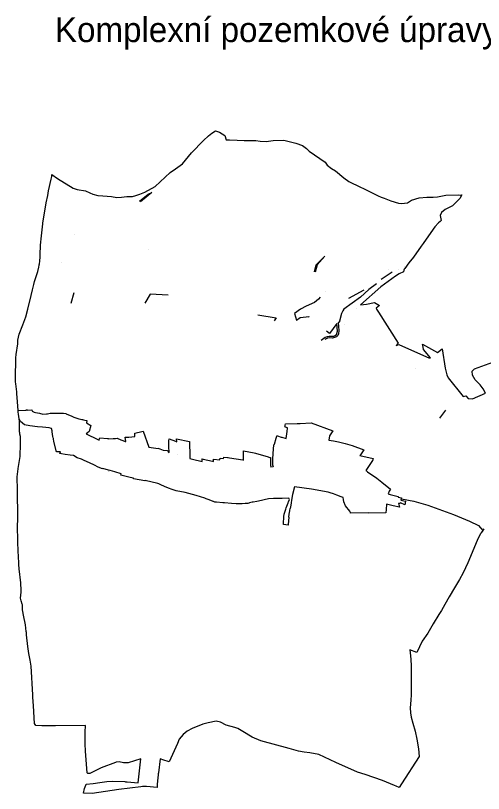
# Model space of a CAD drawing. Extents: x -598799 to -595054, y -1105067 to -1101467.
# Drawn here: x -598799 to -596632, y -1105067 to -1101467 of the extents above; entities that cross this region are included whole.
import ezdxf

# ---------------------------------------------------------------- set-up
doc = ezdxf.new("R2010")
doc.units = 0
for name, color, linetype in [('CESTY', 7, 'Continuous'), ('LES_ZV', 7, 'Continuous'), ('Level 255', 7, 'Continuous'), ('OVNE_PRE', 7, 'Continuous'), ('OVNE_SET', 7, 'Continuous'), ('OVNI_PRE', 7, 'Continuous'), ('OVNI_SET', 7, 'Continuous')]:
    doc.layers.add(name, color=color, linetype=linetype)

msp = doc.modelspace()

# ---------------------------------------------------------------- linework, layer by layer
at = {"layer": 'CESTY'}
msp.add_lwpolyline([(-597012.4, -1103704), (-596954.5, -1103714.7), (-596889.9, -1103733), (-596771.3, -1103775.4), (-596697.2, -1103807), (-596654.8, -1103827.5), (-596634.7, -1103849.3)], dxfattribs=at)
at = {"layer": 'LES_ZV'}
for p, q in [((-598529.5, -1102749.5), (-598542.9, -1102798.7)), ((-597186.3, -1102737.9), (-597257.2, -1102776.5)), ((-597677, -1102852.1), (-597592.2, -1102865.4)), ((-597592.2, -1102865.4), (-597601.3, -1102880.2)), ((-597345.5, -1102937.5), (-597358.4, -1102927.2)), ((-596807.4, -1103293.5), (-596835.8, -1103330.1))]:
    msp.add_line(p, q, dxfattribs=at)
for points in [[(-598225.5, -1102326.3), (-598185.7, -1102294.1), (-598167.7, -1102285.4), (-598220.4, -1102328.6)], [(-597415, -1102652.4), (-597406.7, -1102620.3), (-597367.2, -1102580.1), (-597402.4, -1102620.7), (-597411.3, -1102655.1)], [(-597054.7, -1102654.7), (-597078.6, -1102669.1), (-597105.3, -1102688.8)], [(-597128.3, -1102708.9), (-597162.5, -1102734.2), (-597201.2, -1102769.4), (-597278.6, -1102825.5), (-597283.1, -1102833.7), (-597289.6, -1102846.4), (-597300.9, -1102887.5), (-597305.6, -1102887.7), (-597302.5, -1102924.4)], [(-598092, -1102760.7), (-598175.9, -1102755.8), (-598199.8, -1102798.4)], [(-597387.8, -1102770.8), (-597396.2, -1102779.4), (-597414.6, -1102794.2), (-597453.4, -1102811), (-597479.2, -1102825.4), (-597507.2, -1102845.6), (-597498.6, -1102876.1), (-597481, -1102863.7)], [(-597481, -1102863.7), (-597439.9, -1102859), (-597441.8, -1102862)], [(-597308.9, -1102927.5), (-597311.3, -1102891.3), (-597345.5, -1102937.5)], [(-597384.3, -1102968.8), (-597371.5, -1102959.6), (-597364.9, -1102955), (-597355.1, -1102951.8), (-597347.4, -1102951), (-597332.8, -1102950.8), (-597325, -1102950), (-597319.5, -1102947.8), (-597313.5, -1102943), (-597310.5, -1102937.5), (-597308.9, -1102927.5)], [(-597302.5, -1102924.4), (-597304.3, -1102940.1), (-597307, -1102947.1), (-597312.1, -1102954), (-597330.8, -1102959.5), (-597345.8, -1102958.4), (-597354, -1102959.9), (-597360.7, -1102962.4), (-597366.5, -1102965.4)]]:
    msp.add_lwpolyline(points, dxfattribs=at)
at = {"layer": 'Level 255'}
for p, q in [((-598184.5, -1102548.9), (-598184.5, -1102548.9)), ((-598655.5, -1103310.2), (-598655.5, -1103310.2)), ((-598564.1, -1103309.6), (-598564.1, -1103309.6)), ((-598538.8, -1103321.3), (-598538.8, -1103321.3)), ((-598412.3, -1103431.9), (-598412.3, -1103431.9)), ((-597546.5, -1103424.8), (-597546.5, -1103424.8)), ((-597311.1, -1103438.4), (-597311.1, -1103438.4)), ((-598530.5, -1103503.4), (-598530.5, -1103503.4)), ((-597935, -1103531.2), (-597935, -1103531.2)), ((-597742.8, -1103524.4), (-597742.8, -1103524.4)), ((-597608, -1103526.3), (-597608, -1103526.3)), ((-597608, -1103526.3), (-597608, -1103526.3)), ((-597545.7, -1103745.5), (-597545.7, -1103745.5))]:
    msp.add_line(p, q, dxfattribs=at)
at = {"layer": 'OVNE_PRE'}
for p, q in [((-596747.9, -1102297.1), (-596737.9, -1102297.3)), ((-598525.3, -1102480.3), (-598525.3, -1102480.3)), ((-598184.5, -1102548.9), (-598184.5, -1102548.9)), ((-598584.3, -1102610.6), (-598584.3, -1102610.6)), ((-597027.4, -1102643.9), (-597027.4, -1102643.9)), ((-596998.7, -1102626.4), (-596998.7, -1102626.4)), ((-597363.3, -1102745.5), (-597363.3, -1102745.5)), ((-597202.4, -1102804.9), (-597202.4, -1102804.9)), ((-597276.6, -1102895.5), (-597276.6, -1102895.5)), ((-597007.7, -1102996.6), (-596884.6, -1103051.3)), ((-596945.3, -1103100), (-596945.3, -1103100)), ((-596796, -1103143.9), (-596725.5, -1103230.3)), ((-598368, -1103425), (-598368, -1103425)), ((-598336.9, -1103423.4), (-598336.9, -1103423.4)), ((-598328.9, -1103423), (-598328.9, -1103423)), ((-597992, -1103516.2), (-597992, -1103516.2))]:
    msp.add_line(p, q, dxfattribs=at)
for points in [[(-598673, -1102430.8), (-598672.8, -1102427.8), (-598657.9, -1102333.7), (-598650.3, -1102299.5), (-598646.6, -1102277.3), (-598634, -1102223.4), (-598631.6, -1102212.3), (-598631.2, -1102203.2), (-598605.5, -1102220.4), (-598532.4, -1102265.7), (-598513.8, -1102271.9), (-598474.8, -1102278.1), (-598455.4, -1102287.4), (-598440.6, -1102293.3), (-598417.9, -1102299.4), (-598394.7, -1102301.3), (-598354.3, -1102304.4), (-598330.4, -1102308.4), (-598308.6, -1102307.5), (-598283.3, -1102304.6), (-598257.4, -1102303.9), (-598242.1, -1102299.6), (-598223, -1102293.9), (-598200.3, -1102284.1), (-598153.3, -1102257.4), (-598105.8, -1102214.5), (-598083.2, -1102193.6), (-598059.2, -1102176.2), (-598026.3, -1102153.8), (-597998, -1102118.5), (-597985, -1102102.2), (-597928.8, -1102045.6), (-597905.9, -1102023.6), (-597890.8, -1102010.8), (-597873.2, -1101999.7), (-597854.5, -1102006.4), (-597829.7, -1102021.8), (-597823.8, -1102041.5), (-597808.8, -1102041.3), (-597772.1, -1102043.3), (-597741.1, -1102044.8), (-597718.6, -1102045.3), (-597686.7, -1102045.6), (-597666.1, -1102048.5), (-597639.1, -1102050.1), (-597606.1, -1102045.7), (-597556.4, -1102044.3), (-597500.7, -1102057.7), (-597470.7, -1102068.3), (-597452, -1102081.7), (-597439.5, -1102094.8), (-597365.8, -1102145.8), (-597356.7, -1102158.7), (-597335.8, -1102174.4), (-597317.3, -1102185.5), (-597279.6, -1102217.4), (-597255.5, -1102234.1), (-597201.1, -1102260.6), (-597188.2, -1102266.5), (-597169.4, -1102276.9), (-597134.9, -1102293.7), (-597120.1, -1102300.7), (-597106.2, -1102307.1), (-597092.2, -1102311.9), (-597061, -1102324.5), (-597025.4, -1102334.6), (-597012, -1102336.4), (-596983.8, -1102334), (-596964.7, -1102321.1), (-596930.5, -1102310.1), (-596895, -1102307.6), (-596864.8, -1102307.2), (-596845.6, -1102306.2), (-596807, -1102298.2), (-596747.9, -1102297.1)], [(-598696.8, -1102650.7), (-598691.9, -1102630.5), (-598690.1, -1102622.7), (-598689.3, -1102619.5), (-598689, -1102618.2), (-598686.7, -1102600.1), (-598685.7, -1102586.2), (-598684.9, -1102573.8), (-598683.9, -1102529.1), (-598678.8, -1102486.8), (-598673, -1102430.8)], [(-598772.6, -1104133.3), (-598773.1, -1104124.2), (-598774.6, -1104095.6), (-598775, -1104091.5), (-598782.4, -1104026.6), (-598784.6, -1104007.1), (-598786.3, -1103963.9), (-598786.9, -1103951), (-598787.9, -1103896.2), (-598790, -1103831.6), (-598789.4, -1103796.3), (-598789.3, -1103791.6), (-598790.8, -1103663.4), (-598791, -1103601.5), (-598787.3, -1103564.4), (-598787.2, -1103562.4), (-598778.6, -1103508.1), (-598777.6, -1103487.3), (-598776.5, -1103468.1), (-598776.5, -1103458.9), (-598776.6, -1103446.6), (-598776.6, -1103442.7), (-598776.6, -1103442.3), (-598776.7, -1103421), (-598776.7, -1103414.7), (-598778.7, -1103403.6), (-598779.2, -1103400.9), (-598779.7, -1103398.1), (-598780.6, -1103393), (-598781, -1103391), (-598780.7, -1103365.3), (-598780.5, -1103350.6), (-598780.5, -1103345.6), (-598782.6, -1103332.4), (-598785.9, -1103311.1), (-598787.1, -1103301.7), (-598787.4, -1103299.2), (-598787.7, -1103295.1), (-598790.1, -1103254.7), (-598793.3, -1103216.5), (-598793.8, -1103209.5), (-598794, -1103208.1), (-598798.1, -1103171.4), (-598799.2, -1103161.8), (-598799.2, -1103153.4), (-598799.2, -1103136.3), (-598799.2, -1103132.9), (-598798.1, -1103066.4), (-598797.4, -1103050.3), (-598795.8, -1103036), (-598789, -1102986.1), (-598788.9, -1102968.5), (-598782.8, -1102941.9), (-598765.3, -1102897.4), (-598751.7, -1102860.9), (-598742.5, -1102825.1), (-598726.6, -1102763.1), (-598720.2, -1102735.8), (-598714.5, -1102710.9), (-598711.2, -1102697), (-598699.8, -1102660.2), (-598696.8, -1102650.7)], [(-597202.4, -1102804.9), (-597174.6, -1102802.1), (-597137.5, -1102795.5), (-597113.2, -1102807.9), (-597129.2, -1102821.6), (-597126.9, -1102825.6), (-597118.8, -1102839.5), (-597027.8, -1102982.6), (-597035.8, -1102993.1), (-597023.7, -1102988.4), (-597007.7, -1102996.6)], [(-596884.6, -1103051.3), (-596876.7, -1103050.5), (-596909.5, -1103012.1), (-596913.5, -1102992.2), (-596914.4, -1102987.9)], [(-596914.4, -1102987.9), (-596845.8, -1103026.5), (-596824.1, -1103009.7)], [(-596824.1, -1103009.7), (-596809.4, -1103098.9), (-596802.3, -1103129.4), (-596796, -1103143.9)], [(-596630.9, -1103842.5), (-596633.6, -1103846.6), (-596638.4, -1103853.9), (-596639.7, -1103855.7), (-596642.5, -1103860), (-596643.7, -1103861.8), (-596644.4, -1103862.9), (-596645.8, -1103865.1), (-596658.9, -1103889.1), (-596684.8, -1103951.4), (-596705.1, -1103999.9), (-596725.9, -1104046.1), (-596742.8, -1104077.3), (-596765.7, -1104114.8), (-596790.8, -1104157.4), (-596811.2, -1104192), (-596826.8, -1104219.5), (-596839.4, -1104238.1), (-596865.6, -1104281.1), (-596890.2, -1104325.5), (-596915.4, -1104362.7), (-596941.2, -1104414.1), (-596972.6, -1104402.5), (-596969.6, -1104430.2), (-596968, -1104446.1), (-596967.3, -1104476.7), (-596967.7, -1104528.2), (-596967.7, -1104577.9), (-596967.7, -1104609.8), (-596969.3, -1104635.6), (-596971.4, -1104671.2), (-596970.3, -1104694.2)], [(-598767.8, -1104193.9), (-598768.6, -1104190.8), (-598773.1, -1104174.8), (-598776.5, -1104162.6), (-598772.9, -1104135.5), (-598772.6, -1104133.3)], [(-598767.1, -1104216.9), (-598767.2, -1104213.4), (-598767.7, -1104196.1), (-598767.8, -1104193.9)], [(-598748.1, -1104332.2), (-598749.2, -1104321.3), (-598749.8, -1104316.7), (-598753.2, -1104285.9), (-598762.1, -1104241.8), (-598765.5, -1104224.6), (-598767.1, -1104216.9)], [(-598476.6, -1104783), (-598475.8, -1104753), (-598614, -1104753.8), (-598665.8, -1104754.1), (-598677.9, -1104753.4), (-598705.8, -1104751.9), (-598711.2, -1104743.2), (-598716.2, -1104660.6), (-598718.6, -1104621.6), (-598719.3, -1104609.8), (-598727.2, -1104477), (-598732.1, -1104449.2), (-598737.6, -1104418.4), (-598743, -1104387.3), (-598748.1, -1104332.2)], [(-596970.3, -1104694.2), (-596966.4, -1104713.6), (-596959.8, -1104740.9)], [(-596930.7, -1104896.4), (-597012.1, -1105022.2), (-597023.3, -1105039.1), (-597035.8, -1105033), (-597043.7, -1105029.7), (-597100.4, -1105007.3), (-597180.1, -1104978.9), (-597215.8, -1104967.7), (-597315.6, -1104923.9), (-597395.4, -1104887.1), (-597436.6, -1104878.1), (-597437, -1104879.4), (-597462.4, -1104876.2), (-597489.4, -1104870.4), (-597532.7, -1104859.1), (-597663.9, -1104823.1), (-597703, -1104806.2), (-597746, -1104779.5), (-597769, -1104766.8), (-597784.2, -1104761.6), (-597824.5, -1104751.1), (-597850.6, -1104737.6), (-597870.5, -1104732.1), (-597907.7, -1104739.3), (-597931.1, -1104746.3), (-597980.5, -1104765.4), (-598004.3, -1104778), (-598022.2, -1104793.8), (-598041, -1104815.2), (-598049.8, -1104835.6), (-598087.1, -1104921), (-598091.8, -1104919.5), (-598112, -1104913), (-598129.7, -1104907.3), (-598137.5, -1104971.2), (-598138.1, -1104976.1), (-598139.3, -1104986), (-598139.7, -1104989.6), (-598140.2, -1104993.8), (-598143.7, -1105024.5), (-598143.3, -1105033.1), (-598143.1, -1105039.2), (-598192.1, -1105034.7), (-598210.8, -1105035.3), (-598219.1, -1105035.5), (-598320.5, -1105048.9), (-598443.7, -1105066.7), (-598484, -1105065.9), (-598480.5, -1105044), (-598473, -1105027.8)], [(-596959.8, -1104740.9), (-596948.8, -1104779.1), (-596940.6, -1104815.5), (-596933.4, -1104860.2), (-596930.7, -1104896.4)], [(-598475.5, -1104871.2), (-598476.1, -1104837.6), (-598476.2, -1104827.6), (-598476.6, -1104783)], [(-598408.3, -1105015.9), (-598376.8, -1105011), (-598351.9, -1105009.4), (-598293.4, -1105012.1), (-598290.6, -1105012.3), (-598281.9, -1105012.9), (-598231.8, -1105017.5), (-598218.3, -1104906.7), (-598277.5, -1104925.5), (-598298.9, -1104925.5), (-598318.8, -1104920.9), (-598333, -1104921.8), (-598336.2, -1104923), (-598402.3, -1104948.9), (-598455.3, -1104974.9), (-598463.7, -1104974.9), (-598468, -1104971.1), (-598475.5, -1104871.2)], [(-598473, -1105027.8), (-598471.5, -1105024.4), (-598439.8, -1105021.1), (-598408.3, -1105015.9)]]:
    msp.add_lwpolyline(points, dxfattribs=at)
at = {"layer": 'OVNE_SET'}
for p, q in [((-598673, -1102430.8), (-598673, -1102430.8)), ((-597070.1, -1102641.2), (-597070.1, -1102641.2)), ((-597221.8, -1102820.5), (-597221.8, -1102820.5)), ((-598655.7, -1103310.2), (-598655.7, -1103310.2))]:
    msp.add_line(p, q, dxfattribs=at)
for points in [[(-596737.9, -1102297.3), (-596731.6, -1102297.2), (-596742.2, -1102313), (-596775.4, -1102347.9), (-596810.2, -1102364.8), (-596826.1, -1102378.9), (-596832.9, -1102392.9), (-596829.6, -1102407.2), (-596827.8, -1102415.3), (-596832.8, -1102419.4), (-596840.5, -1102426.4), (-596858.1, -1102444.9), (-596886.4, -1102485.7), (-596911.3, -1102521.8), (-596920, -1102534.1), (-596955.9, -1102584.5), (-596977.4, -1102610.5), (-596996.2, -1102637.5), (-596998.9, -1102640.9), (-597001.4, -1102644.7), (-597002.1, -1102652.6), (-597021.9, -1102661.8)], [(-597021.9, -1102661.8), (-597039.2, -1102673.1), (-597106.8, -1102722.1), (-597202.4, -1102804.9)], [(-596725.5, -1103230.3), (-596713.2, -1103227.4), (-596703.2, -1103238.7), (-596683, -1103241.1), (-596622.8, -1103214.7), (-596632.8, -1103193.8), (-596648.2, -1103175.4), (-596670.2, -1103152.4), (-596682.9, -1103131.8), (-596684.4, -1103113), (-596673.2, -1103102.5), (-596623.5, -1103083.9), (-596589.3, -1103071.3), (-596560, -1103062.9), (-596527.1, -1103054.2), (-596488.9, -1103043.6)]]:
    msp.add_lwpolyline(points, dxfattribs=at)
at = {"layer": 'OVNI_PRE'}
for p, q in [((-598706.2, -1103304.2), (-598689, -1103307.4)), ((-598639.1, -1103307.3), (-598629.4, -1103307.3)), ((-598629.4, -1103307.3), (-598619.5, -1103307.4)), ((-598412.3, -1103431.9), (-598412.3, -1103431.9)), ((-598368, -1103425), (-598368, -1103425)), ((-598048.2, -1103499.6), (-598048.2, -1103499.6)), ((-597204.8, -1103503.4), (-597143, -1103517.4)), ((-597935.6, -1103517.9), (-597935.6, -1103517.9)), ((-598273.9, -1103603.8), (-598310.9, -1103593.7)), ((-597026.6, -1103692.4), (-597026.6, -1103692.4)), ((-597563.7, -1103702.5), (-597567.5, -1103702.4)), ((-597534.1, -1103700.8), (-597563.7, -1103702.5)), ((-597530.3, -1103706.8), (-597534.1, -1103700.8)), ((-597024, -1103730.6), (-597023.7, -1103731.8)), ((-597547.9, -1103750.8), (-597545.7, -1103745.5)), ((-597529.4, -1103759.4), (-597529.4, -1103759.4)), ((-597556.6, -1103784.7), (-597554.6, -1103773.7))]:
    msp.add_line(p, q, dxfattribs=at)
for points in [[(-598787.7, -1103295.1), (-598749.3, -1103293.3), (-598749.4, -1103292), (-598744.5, -1103291.6), (-598744.4, -1103293.1), (-598723.2, -1103292.1), (-598722, -1103297.4), (-598713.6, -1103302.7), (-598706.2, -1103304.2)], [(-598619.5, -1103307.4), (-598585.6, -1103307), (-598576.4, -1103306.9)], [(-598505.5, -1103332.5), (-598499.1, -1103334), (-598491.5, -1103335.9), (-598488.4, -1103336.7), (-598485.3, -1103337.4), (-598479.1, -1103338.9), (-598468.8, -1103341.4), (-598471.1, -1103350.9), (-598451.1, -1103364.2), (-598458.6, -1103391.8), (-598466.2, -1103397.4), (-598472.5, -1103402.1), (-598418.6, -1103428.8), (-598412.3, -1103431.9)], [(-597539, -1103374.6), (-597548.9, -1103371), (-597551.7, -1103370.1), (-597551, -1103366.4), (-597550.1, -1103362.4), (-597549, -1103356.8), (-597494.9, -1103354.5), (-597487.6, -1103354.2), (-597481, -1103354), (-597430.2, -1103351.9), (-597329.1, -1103388.7), (-597344.8, -1103411.4), (-597348.8, -1103431.3), (-597326.6, -1103435.4), (-597311.1, -1103438.4)], [(-598624.4, -1103421.4), (-598626.1, -1103414.7), (-598626.7, -1103412.4), (-598628.8, -1103409.2), (-598630.4, -1103388.4), (-598633, -1103377.1)], [(-598328.9, -1103423), (-598311, -1103430.6), (-598302.1, -1103434.1), (-598292.2, -1103437.5), (-598288, -1103437.6), (-598291.1, -1103417.7), (-598274.5, -1103418), (-598247.2, -1103414.4), (-598246.8, -1103407.4), (-598246.6, -1103404.9), (-598246.3, -1103400.2), (-598214.3, -1103391.9), (-598208.3, -1103390.4), (-598181.8, -1103464.9), (-598138.6, -1103470.6), (-598138.7, -1103468.6), (-598115.3, -1103477.4)], [(-597546.5, -1103424.8), (-597541.5, -1103391.5), (-597539.2, -1103375.9), (-597539, -1103374.6)], [(-598623.5, -1103426.7), (-598623.8, -1103424.6), (-598624.4, -1103421.4)], [(-598569.4, -1103498.6), (-598586.7, -1103495.6), (-598594.8, -1103494.2), (-598590.3, -1103485.8), (-598609.9, -1103486.2), (-598621.7, -1103437.8), (-598621.8, -1103437.1), (-598623.5, -1103426.7)], [(-598412.3, -1103431.9), (-598410.2, -1103426.3), (-598408.3, -1103420.9), (-598373.3, -1103424.3)], [(-598373.3, -1103424.3), (-598370.4, -1103424), (-598368, -1103425), (-598346.5, -1103423.9), (-598336.9, -1103423.4), (-598328.9, -1103423)], [(-598096.6, -1103479.6), (-598092.6, -1103481), (-598091.8, -1103486.2), (-598087.5, -1103488.9), (-598088.4, -1103483.8), (-598089.5, -1103466.2), (-598089.7, -1103444.4), (-598089.2, -1103435.5), (-598087.8, -1103426.3)], [(-598087.8, -1103426.3), (-598075, -1103430.4), (-598066.4, -1103433.5), (-598052.8, -1103438.9), (-598053.1, -1103426.2)], [(-598053.1, -1103426.2), (-597993.7, -1103438.2), (-597992.2, -1103507.8), (-597992, -1103516.2)], [(-597600.6, -1103450.1), (-597592.3, -1103423), (-597590.9, -1103418.2), (-597588.8, -1103411.4), (-597585.3, -1103412.1), (-597569.7, -1103417.3), (-597565.3, -1103418.7), (-597546.5, -1103424.8)], [(-597311.1, -1103438.4), (-597304.1, -1103440.2), (-597273.4, -1103447.9)], [(-598115.3, -1103477.4), (-598096.6, -1103479.6), (-598092.6, -1103481), (-598091.8, -1103486.2)], [(-597606.2, -1103497.4), (-597605.7, -1103493), (-597604.8, -1103473.3), (-597602.9, -1103453.6)], [(-597273.4, -1103447.9), (-597241, -1103456.1), (-597186.6, -1103476.1)], [(-597186.6, -1103476.1), (-597202.2, -1103499.4), (-597204.8, -1103503.4)], [(-598530.5, -1103503.4), (-598546.8, -1103501.4), (-598569.4, -1103498.6)], [(-598493.8, -1103520.2), (-598513.2, -1103512.9), (-598530.5, -1103503.4)], [(-597935.6, -1103517.9), (-597930.7, -1103519.1), (-597886.6, -1103529.4), (-597882.2, -1103530.1), (-597882.3, -1103520.4), (-597852.7, -1103523.1), (-597852, -1103515.4), (-597835.6, -1103516.1), (-597835.2, -1103510.2), (-597817, -1103512.4), (-597813.9, -1103512.7), (-597808.7, -1103514.2), (-597746.6, -1103522.3), (-597742.8, -1103524.4)], [(-597742.8, -1103481.9), (-597694.2, -1103490.9), (-597688.4, -1103492), (-597629.5, -1103508.5), (-597625.7, -1103510.4), (-597622, -1103512.3), (-597618.4, -1103512.7), (-597617.8, -1103513), (-597618.8, -1103524.6)], [(-597742.8, -1103524.4), (-597742.8, -1103523.4), (-597742.8, -1103495.1), (-597742.8, -1103481.9)], [(-597608, -1103526.3), (-597607.4, -1103516.3), (-597606.2, -1103497.4)], [(-598456.4, -1103537), (-598482.1, -1103525.4), (-598484.6, -1103524.3), (-598493.8, -1103520.2)], [(-598395, -1103564.3), (-598401, -1103562.2), (-598419.8, -1103554.6), (-598430.5, -1103549.4), (-598433.2, -1103547.9), (-598456.4, -1103537)], [(-597992, -1103516.2), (-597979.1, -1103519.5), (-597935, -1103531.2)], [(-597935, -1103531.2), (-597935.3, -1103524.2), (-597935.6, -1103517.9)], [(-597618.8, -1103524.6), (-597618, -1103549.7), (-597617.7, -1103557.2)], [(-597149.4, -1103531.3), (-597177.1, -1103572), (-597173.6, -1103574.5), (-597169.1, -1103577.7), (-597125.3, -1103608.3), (-597103.5, -1103625.8), (-597063, -1103658.2), (-597069.6, -1103668.4), (-597071, -1103671.9), (-597072.3, -1103675.3), (-597074.1, -1103680.1)], [(-597143, -1103517.4), (-597145.2, -1103522.1), (-597149.4, -1103531.3)], [(-598253.3, -1103608.3), (-598268.2, -1103605.1), (-598273.9, -1103603.8)], [(-598099.1, -1103650.2), (-598123.5, -1103639.4), (-598135.6, -1103634.1), (-598140.8, -1103632.8), (-598198.4, -1103618.9), (-598201.2, -1103620.4), (-598253.7, -1103610.2), (-598253.3, -1103608.3)], [(-598078, -1103658.6), (-598085.9, -1103655.4), (-598099.1, -1103650.2)], [(-598030.5, -1103670.8), (-598054.6, -1103666.4), (-598078, -1103658.6)], [(-597350.9, -1103672.3), (-597429.2, -1103657.9), (-597507.5, -1103647.8), (-597517.2, -1103682.6), (-597521.5, -1103708.9), (-597523, -1103722), (-597524.7, -1103732.1), (-597527.9, -1103748.7)], [(-598013.6, -1103673.9), (-598020.9, -1103672.5), (-598030.5, -1103670.8)], [(-597921.9, -1103700.9), (-597963, -1103688.5), (-598013.6, -1103673.9)], [(-597290.5, -1103694.1), (-597311.5, -1103686.5), (-597327.1, -1103680.9), (-597342.5, -1103675.4), (-597350.9, -1103672.3)], [(-597022.4, -1103737.7), (-597021.6, -1103741.4), (-597049.7, -1103735.7), (-597081.7, -1103728.4), (-597083.4, -1103753.2), (-597083.5, -1103755.2), (-597084.2, -1103764.4), (-597084.5, -1103768.4), (-597164.7, -1103769.6), (-597164.6, -1103767.7), (-597247.8, -1103770.1), (-597248.7, -1103766.2), (-597251.3, -1103760.8), (-597271.4, -1103735.1), (-597278.5, -1103717.8), (-597280.8, -1103705.8), (-597282, -1103697.3), (-597290.5, -1103694.1)], [(-597026.6, -1103692.4), (-597027.2, -1103695.6), (-597012.3, -1103698.9)], [(-597902.2, -1103708.2), (-597915.9, -1103703.1), (-597921.9, -1103700.9)], [(-597876.1, -1103718.8), (-597882, -1103716.4), (-597884.3, -1103715.6), (-597902.2, -1103708.2)], [(-597839.1, -1103721.9), (-597868.6, -1103719.4), (-597876.1, -1103718.8)], [(-597776.9, -1103726.9), (-597798.7, -1103725.3), (-597831.1, -1103722.5), (-597839.1, -1103721.9)], [(-597699.3, -1103718), (-597703.5, -1103718.6), (-597703.4, -1103719.1), (-597715.5, -1103722.6), (-597719.2, -1103723.4), (-597724.2, -1103724.2), (-597730.5, -1103725), (-597736, -1103725.5)], [(-597604.2, -1103701.9), (-597628.1, -1103703.6), (-597674.7, -1103713.9)], [(-597567.5, -1103702.4), (-597589.9, -1103702.1), (-597604.2, -1103701.9)], [(-597012.3, -1103698.9), (-597014.2, -1103710.2), (-596993.6, -1103713.4), (-596996.5, -1103730.9), (-597016.1, -1103721.5), (-597017.2, -1103724.3), (-597021.8, -1103724.6), (-597025.1, -1103725.7), (-597024, -1103730.6)], [(-597554.6, -1103773.7), (-597553.2, -1103768.9), (-597547.9, -1103750.8)], [(-597533.4, -1103788.3), (-597531.4, -1103773.7), (-597529.4, -1103759.4)], [(-597529.4, -1103759.4), (-597529.2, -1103757.8), (-597527.9, -1103748.7)], [(-597023.7, -1103731.8), (-597023.1, -1103734.6), (-597022.4, -1103737.7)], [(-597557.8, -1103821.7), (-597557.7, -1103818.5), (-597556.6, -1103784.7)], [(-597533.4, -1103788.3), (-597535.9, -1103821.5), (-597536.2, -1103824.6), (-597557.8, -1103821.7)]]:
    msp.add_lwpolyline(points, dxfattribs=at)
at = {"layer": 'OVNI_SET'}
for p, q in [((-598564.1, -1103309.6), (-598538.8, -1103321.3)), ((-598510.5, -1103331.4), (-598505.5, -1103332.5)), ((-598778.7, -1103403.6), (-598778.7, -1103403.6)), ((-598633, -1103377.1), (-598643.6, -1103374.6)), ((-597539, -1103374.6), (-597539, -1103374.6)), ((-598623.5, -1103426.7), (-598623.5, -1103426.7)), ((-597311.1, -1103438.4), (-597311.1, -1103438.4)), ((-597602.9, -1103453.6), (-597602.9, -1103453.6)), ((-597273.4, -1103447.9), (-597273.4, -1103447.9)), ((-597606.2, -1103497.4), (-597606.2, -1103497.4)), ((-597204.8, -1103503.4), (-597204.8, -1103503.4)), ((-597992, -1103516.2), (-597992, -1103516.2)), ((-597936.1, -1103517), (-597936.1, -1103517)), ((-597935, -1103531.2), (-597935, -1103531.2)), ((-597742.8, -1103524.4), (-597742.8, -1103524.4)), ((-597608.1, -1103549.4), (-597608, -1103526.3)), ((-597149.4, -1103531.3), (-597149.4, -1103531.3)), ((-597149.4, -1103531.3), (-597149.4, -1103531.3)), ((-598361, -1103572.6), (-598368.3, -1103570.1)), ((-598339.6, -1103579), (-598361, -1103572.6)), ((-597026.6, -1103692.4), (-597026.6, -1103692.4)), ((-597535.2, -1103717.5), (-597530.3, -1103706.8)), ((-597024, -1103730.6), (-597024, -1103730.6))]:
    msp.add_line(p, q, dxfattribs=at)
for points in [[(-598643.6, -1103374.6), (-598674.7, -1103371.3), (-598697.7, -1103369.8), (-598733.3, -1103366.1), (-598758.5, -1103361.1), (-598776.6, -1103345.6), (-598782.6, -1103332.4)], [(-598689, -1103307.4), (-598673.3, -1103311.2), (-598655.7, -1103310.2)], [(-598655.7, -1103310.2), (-598651, -1103309.3), (-598639.1, -1103307.3)], [(-598576.4, -1103306.9), (-598566.6, -1103309), (-598564.1, -1103309.6)], [(-598538.8, -1103321.3), (-598528.9, -1103325.1), (-598510.5, -1103331.4)], [(-597602.9, -1103453.6), (-597602.2, -1103452.5), (-597600.6, -1103450.1)], [(-597608.1, -1103549.4), (-597605.8, -1103555.1), (-597617.7, -1103557.2)], [(-598368.3, -1103570.1), (-598394.4, -1103562.2), (-598395, -1103564.3)], [(-598310.9, -1103593.7), (-598309.4, -1103588.4), (-598339.6, -1103579)], [(-597074.1, -1103680.1), (-597063.5, -1103682.8), (-597026.6, -1103692.4)], [(-597736, -1103725.5), (-597749.7, -1103726), (-597776.9, -1103726.9)], [(-597674.7, -1103713.9), (-597681.5, -1103715), (-597699.3, -1103718)], [(-597545.7, -1103745.5), (-597537.3, -1103722.6), (-597536.4, -1103720.2), (-597535.2, -1103717.5)]]:
    msp.add_lwpolyline(points, dxfattribs=at)

# ---------------------------------------------------------------- texts
at = {"layer": 'Level 255'}
for s, height, p in [('Komplexní pozemkové úpravy v k.ú. Sklené u Svitav', 114.7, (-598616.7, -1101589.7)), ('GP', 3, (-598369.1, -1103576.8))]:
    msp.add_text(s, height=height, dxfattribs=at).set_placement(p)

doc.saveas('drawing.dxf')
